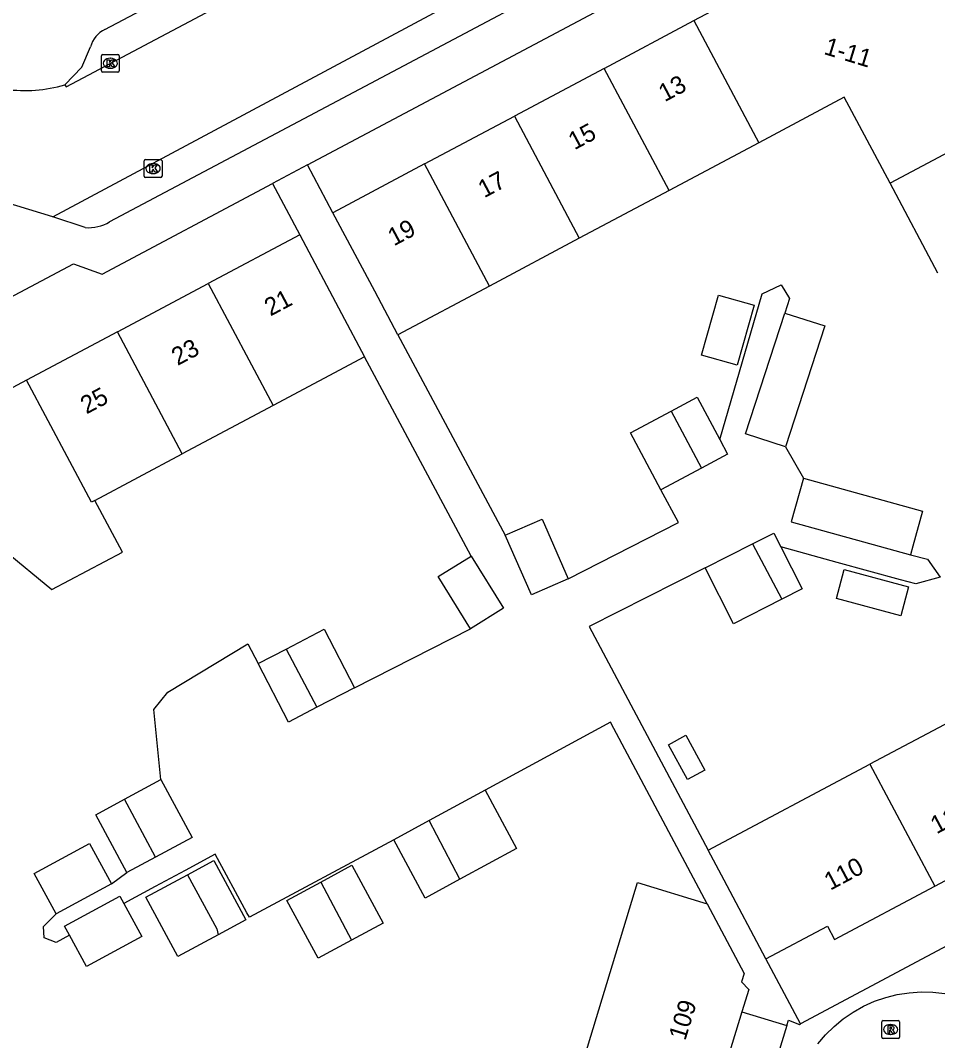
# Model space of a CAD drawing. Extents: x 160304 to 160954, y 383686 to 384161.
# Drawn here: x 160728.7 to 160780.3, y 383795.3 to 383852.6 of the extents above; entities that cross this region are included whole.
import ezdxf

# ---------------------------------------------------------------- set-up
doc = ezdxf.new("R2010")
doc.units = 0
for name, color, linetype in [('IMGEO_Kolk', 7, 'Continuous'), ('IMGEO_Pand', 7, 'Continuous'), ('IMGEO_Pand_nummerreeks', 7, 'Continuous'), ('IMGEO_Rijbaan_lokaal_open', 7, 'Continuous'), ('IMGEO_Rioolput', 7, 'Continuous'), ('IMGEO_Voetpad_open', 7, 'Continuous')]:
    doc.layers.add(name, color=color, linetype=linetype)

msp = doc.modelspace()

# ---------------------------------------------------------------- linework, layer by layer
at = {"layer": 'IMGEO_Kolk'}
for p, q in [((160733.348, 383850.724), (160734.2, 383850.724)), ((160733.273, 383849.798), (160733.273, 383850.65)), ((160733.761, 383850.504), (160733.786, 383850.504)), ((160734.274, 383850.65), (160734.274, 383849.798)), ((160734.2, 383849.724), (160733.348, 383849.724)), ((160733.784, 383849.944), (160733.759, 383849.944)), ((160735.675, 383843.886), (160735.675, 383844.738)), ((160735.75, 383844.812), (160736.602, 383844.812)), ((160736.163, 383844.592), (160736.188, 383844.592)), ((160736.676, 383844.738), (160736.676, 383843.886)), ((160736.186, 383844.032), (160736.161, 383844.032)), ((160736.602, 383843.812), (160735.75, 383843.812))]:
    msp.add_line(p, q, dxfattribs=at)
for points in [[(160733.348, 383850.724), (160734.2, 383850.724)], [(160733.273, 383849.798), (160733.273, 383850.65)], [(160733.594, 383850.424), (160733.717, 383850.424), (160733.717, 383850.273), (160733.847, 383850.424), (160734.011, 383850.424), (160733.865, 383850.273), (160734.018, 383850.024), (160733.866, 383850.024), (160733.781, 383850.188), (160733.717, 383850.121), (160733.717, 383850.024), (160733.594, 383850.024), (160733.594, 383850.424)], [(160734.274, 383850.65), (160734.274, 383849.798)], [(160734.2, 383849.724), (160733.348, 383849.724)], [(160735.675, 383843.886), (160735.675, 383844.738)], [(160735.75, 383844.812), (160736.602, 383844.812)], [(160735.996, 383844.512), (160736.119, 383844.512), (160736.119, 383844.361), (160736.249, 383844.512), (160736.413, 383844.512), (160736.267, 383844.361), (160736.42, 383844.112), (160736.268, 383844.112), (160736.183, 383844.276), (160736.119, 383844.209), (160736.119, 383844.112), (160735.996, 383844.112), (160735.996, 383844.512)], [(160736.676, 383844.738), (160736.676, 383843.886)], [(160736.602, 383843.812), (160735.75, 383843.812)]]:
    msp.add_lwpolyline(points, dxfattribs=at)
for centre, start, end in [((160733.35, 383850.648), 91.55205, 178.44795), ((160733.35, 383850.648), 91.55205, 178.44795), ((160734.198, 383850.648), 1.55205, 88.44795), ((160734.198, 383850.648), 1.55205, 88.44795), ((160733.35, 383849.8), 181.55205, 268.44795), ((160733.35, 383849.8), 181.55205, 268.44795), ((160734.198, 383849.8), 271.55205, 358.44795), ((160734.198, 383849.8), 271.55205, 358.44795), ((160735.752, 383844.736), 91.55205, 178.44795), ((160735.752, 383844.736), 91.55205, 178.44795), ((160736.6, 383844.736), 1.55205, 88.44795), ((160736.6, 383844.736), 1.55205, 88.44795), ((160735.752, 383843.888), 181.55205, 268.44795), ((160735.752, 383843.888), 181.55205, 268.44795), ((160736.6, 383843.888), 271.55205, 358.44795), ((160736.6, 383843.888), 271.55205, 358.44795)]:
    msp.add_arc(centre, 0.0765, start, end, dxfattribs=at)
for centre, major_axis, ratio, start_param, end_param in [((160733.76, 383850.224), (-0.387, 0.002), 0.722429, 4.712389, 7.853982), ((160733.785, 383850.224), (-0.39, 0.002), 0.717154, 1.570796, 4.712389), ((160736.162, 383844.312), (-0.387, 0.002), 0.722429, 4.712389, 7.853982), ((160736.187, 383844.312), (-0.39, 0.002), 0.717154, 1.570796, 4.712389)]:
    msp.add_ellipse(centre, major_axis=major_axis, ratio=ratio, start_param=start_param, end_param=end_param, dxfattribs=at)
at = {"layer": 'IMGEO_Pand'}
for points in [[(160766.568, 383852.624), (160772.352, 383855.702)], [(160761.524, 383849.94), (160766.568, 383852.624)], [(160766.568, 383852.624), (160770.217, 383845.765)], [(160761.524, 383849.94), (160756.478, 383847.255)], [(160765.172, 383843.081), (160761.524, 383849.94)], [(160777.597, 383843.482), (160775.022, 383848.322), (160770.217, 383845.765)], [(160751.433, 383844.57), (160756.478, 383847.255)], [(160756.478, 383847.255), (160760.126, 383840.396)], [(160784.479, 383847.144), (160777.597, 383843.482)], [(160770.217, 383845.765), (160765.172, 383843.081)], [(160751.433, 383844.57), (160746.282, 383841.829)], [(160755.081, 383837.711), (160751.433, 383844.57)], [(160780.281, 383838.438), (160777.597, 383843.482)], [(160765.172, 383843.081), (160760.126, 383840.396)], [(160749.931, 383834.971), (160748.631, 383837.415), (160746.282, 383841.829)], [(160744.418, 383840.589), (160739.273, 383837.851)], [(160744.418, 383840.589), (160746.767, 383836.176), (160748.064, 383833.738)], [(160760.126, 383840.396), (160755.081, 383837.711)], [(160734.168, 383835.135), (160739.273, 383837.851)], [(160739.273, 383837.851), (160742.918, 383831)], [(160755.081, 383837.711), (160749.931, 383834.971)], [(160767.944, 383837.192), (160769.946, 383836.63), (160769.004, 383833.27), (160767.002, 383833.832), (160767.944, 383837.192)], [(160771.724, 383828.682), (160769.477, 383829.409), (160771.674, 383836.196)], [(160771.674, 383836.196), (160773.922, 383835.469), (160771.724, 383828.682)], [(160734.168, 383835.135), (160729.062, 383832.418)], [(160737.813, 383828.283), (160734.168, 383835.135)], [(160748.064, 383833.738), (160742.918, 383831)], [(160729.062, 383832.418), (160721.24, 383828.255)], [(160732.906, 383825.673), (160732.708, 383825.567), (160729.062, 383832.418)], [(160765.289, 383830.688), (160766.751, 383831.469), (160768.023, 383829.088)], [(160742.918, 383831), (160737.813, 383828.283)], [(160764.709, 383826.266), (160763, 383829.464), (160765.289, 383830.688)], [(160765.289, 383830.688), (160766.992, 383827.486)], [(160768.023, 383829.088), (160768.46, 383828.271), (160766.992, 383827.486)], [(160732.906, 383825.673), (160737.813, 383828.283)], [(160766.992, 383827.486), (160764.709, 383826.266)], [(160772.719, 383826.913), (160772.043, 383824.473), (160778.732, 383822.62)], [(160772.719, 383826.913), (160779.409, 383825.057), (160778.866, 383823.102), (160778.732, 383822.62)], [(160727.801, 383822.868), (160730.488, 383820.662), (160734.451, 383822.771), (160732.906, 383825.673)], [(160755.97, 383823.719), (160758.045, 383824.622), (160759.509, 383821.261)], [(160769.866, 383823.23), (160771.064, 383823.836), (160771.459, 383823.057)], [(160759.509, 383821.261), (160757.433, 383820.358), (160755.97, 383823.719)], [(160767.206, 383821.883), (160769.866, 383823.23)], [(160769.866, 383823.23), (160771.519, 383820.124)], [(160771.459, 383823.057), (160772.653, 383820.698), (160771.519, 383820.124)], [(160754.007, 383818.464), (160752.196, 383821.393), (160754.051, 383822.54)], [(160754.051, 383822.54), (160755.863, 383819.611), (160754.007, 383818.464)], [(160771.519, 383820.124), (160768.795, 383818.745), (160767.206, 383821.883)], [(160775.015, 383821.783), (160778.636, 383820.815), (160778.198, 383819.176), (160774.58, 383820.158), (160775.015, 383821.783)], [(160743.647, 383817.315), (160745.792, 383818.43), (160747.499, 383815.146)], [(160742.081, 383816.502), (160743.647, 383817.315)], [(160743.647, 383817.315), (160745.386, 383814.047)], [(160745.386, 383814.047), (160743.788, 383813.217), (160742.081, 383816.502)], [(160747.499, 383815.146), (160745.386, 383814.047)], [(160780.945, 383813.238), (160776.454, 383810.849)], [(160767.186, 383810.516), (160766.216, 383809.984), (160765.14, 383811.944), (160766.11, 383812.476), (160767.186, 383810.516)], [(160767.368, 383806.014), (160776.454, 383810.849)], [(160776.454, 383810.849), (160780.1, 383803.997)], [(160734.576, 383808.884), (160736.615, 383809.985)], [(160736.615, 383809.985), (160738.368, 383806.739), (160736.309, 383805.627)], [(160734.705, 383804.761), (160732.953, 383808.007), (160734.576, 383808.884)], [(160736.309, 383805.627), (160734.576, 383808.884)], [(160754.835, 383809.383), (160751.681, 383807.679)], [(160754.835, 383809.383), (160756.603, 383806.111), (160753.418, 383804.39)], [(160751.681, 383807.679), (160749.695, 383806.607)], [(160753.418, 383804.39), (160751.681, 383807.679)], [(160753.418, 383804.39), (160751.462, 383803.334), (160749.695, 383806.607)], [(160730.731, 383802.443), (160729.494, 383804.719), (160732.595, 383806.403), (160733.831, 383804.128)], [(160770.612, 383799.917), (160768.263, 383804.332), (160767.368, 383806.014)], [(160780.1, 383803.997), (160784.591, 383806.386)], [(160736.309, 383805.627), (160734.705, 383804.761)], [(160738.111, 383804.641), (160739.586, 383805.438), (160741.387, 383802.103), (160739.826, 383801.26)], [(160745.608, 383804.231), (160747.352, 383805.173), (160749.105, 383801.927), (160747.332, 383800.969)], [(160739.826, 383801.26), (160737.567, 383800.04), (160735.766, 383803.375), (160738.111, 383804.641)], [(160738.111, 383804.641), (160739.756, 383801.596), (160739.826, 383801.26)], [(160733.831, 383804.128), (160730.731, 383802.443)], [(160747.332, 383800.969), (160745.443, 383799.949), (160743.69, 383803.195), (160745.608, 383804.231)], [(160745.608, 383804.231), (160747.332, 383800.969)], [(160760.453, 383794.532), (160763.405, 383804.2), (160767.315, 383803.007)], [(160770.612, 383799.917), (160774.076, 383801.76), (160774.478, 383801.005), (160780.1, 383803.997)], [(160731.483, 383801.242), (160731.204, 383801.755), (160734.305, 383803.439), (160734.533, 383803.02)], [(160734.533, 383803.02), (160735.541, 383801.164), (160732.441, 383799.479), (160731.483, 383801.242)], [(160767.315, 383803.007), (160769.395, 383799.097), (160769.248, 383798.616), (160769.65, 383798.186), (160769.268, 383796.935)], [(160769.268, 383796.935), (160767.846, 383792.276)]]:
    msp.add_lwpolyline(points, dxfattribs=at)
at = {"layer": 'IMGEO_Rijbaan_lokaal_open'}
for points in [[(160731.211, 383849.019), (160731.287, 383848.905), (160754.245, 383861.066)], [(160730.535, 383841.591), (160757.047, 383855.787)], [(160730.535, 383841.591), (160726.037, 383842.971)], [(160773.535, 383795.135), (160773.968, 383795.648), (160774.444, 383796.12), (160774.962, 383796.548), (160775.515, 383796.927), (160776.1, 383797.256), (160776.712, 383797.532), (160777.347, 383797.751), (160777.998, 383797.913), (160778.661, 383798.016), (160779.331, 383798.06), (160780.002, 383798.043), (160780.669, 383797.967), (160781.326, 383797.831), (160786.462, 383796.304), (160786.776, 383796.249), (160787.094, 383796.223), (160787.412, 383796.225), (160787.73, 383796.256), (160788.043, 383796.315), (160788.35, 383796.402), (160788.583, 383796.488)]]:
    msp.add_lwpolyline(points, dxfattribs=at)
msp.add_arc((160728.961, 383856.676), 7.981, 262.26389, 286.3727, dxfattribs=at)
at = {"layer": 'IMGEO_Rioolput'}
for p, q in [((160777.123, 383795.52), (160777.123, 383796.372)), ((160777.198, 383796.446), (160778.05, 383796.446)), ((160778.124, 383796.372), (160778.124, 383795.52)), ((160777.611, 383796.226), (160777.636, 383796.226)), ((160778.05, 383795.446), (160777.198, 383795.446)), ((160777.634, 383795.666), (160777.609, 383795.666))]:
    msp.add_line(p, q, dxfattribs=at)
for points in [[(160777.123, 383795.52), (160777.123, 383796.372)], [(160777.198, 383796.446), (160778.05, 383796.446)], [(160778.124, 383796.372), (160778.124, 383795.52)], [(160777.712, 383796.144), (160777.46, 383796.146), (160777.46, 383795.746)], [(160777.46, 383795.746), (160777.584, 383795.746), (160777.584, 383795.908), (160777.595, 383795.908)], [(160777.638, 383796.065), (160777.584, 383796.065), (160777.584, 383795.984)], [(160777.584, 383795.984), (160777.636, 383795.984)], [(160777.642, 383795.879), (160777.713, 383795.746), (160777.853, 383795.746), (160777.788, 383795.872)], [(160778.05, 383795.446), (160777.198, 383795.446)]]:
    msp.add_lwpolyline(points, dxfattribs=at)
for centre, radius, start, end in [((160777.2, 383796.37), 0.0765, 91.55205, 178.44795), ((160777.2, 383796.37), 0.0765, 91.55205, 178.44795), ((160778.048, 383796.37), 0.0765, 1.55205, 88.44795), ((160778.048, 383796.37), 0.0765, 1.55205, 88.44795), ((160777.594, 383795.855), 0.0533, 26.02933, 88.69889), ((160777.62, 383796.173), 0.19, 274.7715, 282.96867), ((160777.644, 383795.969), 0.0964, 77.00612, 93.18647), ((160777.658, 383796.026), 0.0378, 276.66336, 79.67722), ((160777.711, 383796.034), 0.109, 350.36119, 89.41601), ((160777.709, 383796.034), 0.112, 277.58423, 350.98172), ((160777.693, 383795.819), 0.108, 29.51342, 73.79051), ((160777.2, 383795.522), 0.0765, 181.55205, 268.44795), ((160777.2, 383795.522), 0.0765, 181.55205, 268.44795), ((160778.048, 383795.522), 0.0765, 271.55205, 358.44795), ((160778.048, 383795.522), 0.0765, 271.55205, 358.44795)]:
    msp.add_arc(centre, radius, start, end, dxfattribs=at)
for centre, major_axis, ratio, start_param, end_param in [((160777.61, 383795.946), (-0.387, 0.002), 0.722429, 4.712389, 7.853982), ((160777.635, 383795.946), (-0.39, 0.002), 0.717154, 1.570796, 4.712389)]:
    msp.add_ellipse(centre, major_axis=major_axis, ratio=ratio, start_param=start_param, end_param=end_param, dxfattribs=at)
at = {"layer": 'IMGEO_Voetpad_open'}
for points in [[(160733.471, 383852.131), (160774.755, 383873.894), (160779.318, 383876.481), (160782.88, 383878.574), (160786.444, 383880.665)], [(160777.692, 383864.638), (160733.727, 383841.315)], [(160744.852, 383844.521), (160770.995, 383858.413), (160772.352, 383855.702)], [(160731.211, 383849.019), (160732.174, 383850.012), (160732.658, 383851.141)], [(160744.852, 383844.521), (160742.884, 383843.475)], [(160746.282, 383841.829), (160744.852, 383844.521)], [(160717.579, 383831.466), (160731.697, 383838.95), (160733.308, 383838.386), (160742.884, 383843.475)], [(160742.884, 383843.475), (160744.418, 383840.589)], [(160732.356, 383840.999), (160730.535, 383841.591)], [(160768.023, 383829.088), (160770.396, 383837.266), (160771.467, 383837.786), (160771.939, 383837.015), (160771.674, 383836.196)], [(160749.931, 383834.971), (160755.97, 383823.719)], [(160754.051, 383822.54), (160748.064, 383833.738)], [(160771.724, 383828.682), (160772.719, 383826.913)], [(160759.509, 383821.261), (160765.694, 383824.422), (160764.709, 383826.266)], [(160778.732, 383822.62), (160779.699, 383822.36), (160780.408, 383821.364), (160779.047, 383820.981), (160778.174, 383821.209), (160774.617, 383822.188), (160771.459, 383823.057)], [(160767.206, 383821.883), (160760.682, 383818.579), (160767.368, 383806.014)], [(160747.499, 383815.146), (160754.007, 383818.464)], [(160736.615, 383809.985), (160736.207, 383813.929), (160737.001, 383814.906), (160741.503, 383817.614), (160742.081, 383816.502)], [(160767.315, 383803.007), (160762.072, 383812.862), (160761.883, 383813.218), (160754.835, 383809.383)], [(160795.736, 383812.317), (160797.261, 383809.435), (160772.561, 383796.263)], [(160749.695, 383806.607), (160741.584, 383802.254), (160741.446, 383802.509), (160739.669, 383805.799), (160737.979, 383804.886), (160736.288, 383803.974), (160734.533, 383803.02)], [(160733.831, 383804.128), (160734.705, 383804.761)], [(160731.483, 383801.242), (160730.736, 383800.836), (160730.049, 383801.103), (160730.01, 383801.733), (160730.731, 383802.443)], [(160772.561, 383796.263), (160770.612, 383799.917)], [(160769.268, 383796.935), (160771.796, 383796.164)], [(160771.796, 383796.164), (160771.888, 383796.465), (160772.509, 383796.235), (160772.561, 383796.263)], [(160771.796, 383796.164), (160766.765, 383779.761), (160764.245, 383780.484)]]:
    msp.add_lwpolyline(points, dxfattribs=at)
for centre, radius, start, end in [((160734.117, 383850.772), 1.505, 115.41116, 165.80233), ((160732.552, 383843.28), 2.29, 265.08675, 300.87196)]:
    msp.add_arc(centre, radius, start, end, dxfattribs=at)

# ---------------------------------------------------------------- texts
at = {"layer": 'IMGEO_Pand_nummerreeks'}
for s, rotation, p in [('1-11', 343.03472, (160773.821, 383850.755)), ('13', 28.01588, (160764.924, 383848.033)), ('15', 28.01588, (160759.853, 383845.334)), ('17', 28.01588, (160754.781, 383842.636)), ('19', 28.01588, (160749.709, 383839.937)), ('21', 28.02056, (160742.77, 383835.996)), ('23', 28.02056, (160737.551, 383833.219)), ('25', 28.02337, (160732.433, 383830.495)), ('111', 28.01764, (160780.206, 383806.907)), ('110', 28.01884, (160774.233, 383803.74)), ('109', 73.02347, (160766.083, 383795.283))]:
    msp.add_text(s, height=1, rotation=rotation, dxfattribs=at).set_placement(p)

doc.saveas('drawing.dxf')
